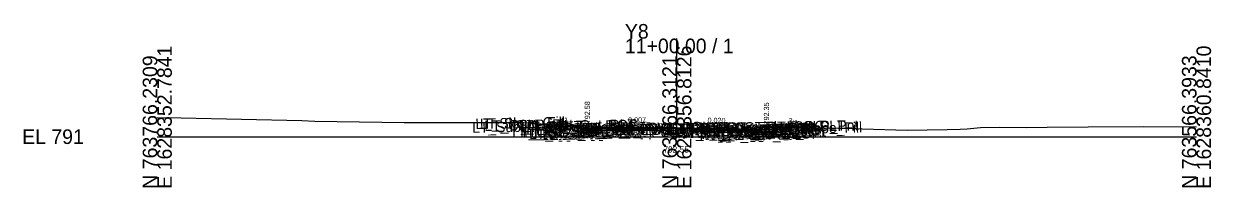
# Model space of a CAD drawing. Extents: x -26 to 203, y -10 to 3017.
# Drawn here: x -25.7 to 202.8, y 1990.3 to 2021.7 of the extents above; entities that cross this region are included whole.
import ezdxf

# ---------------------------------------------------------------- set-up
doc = ezdxf.new("R2010")
doc.units = 0
for name, color, linetype in [('Default', 7, 'Continuous'), ('Exist CMT Pavement', 7, 'Continuous'), ('Exist Cross Section Cell', 7, 'Continuous'), ('Exist XS Center Line Elevation Label', 7, 'Continuous'), ('Exist XS Ground Line', 7, 'Continuous'), ('Prop CMT Conc Surface', 7, 'Continuous'), ('Prop CMT Concrete Structures', 7, 'Continuous'), ('Prop CMT Pvmt Course 1', 7, 'Continuous'), ('Prop CMT Pvmt Course 1 CG', 7, 'Continuous'), ('Prop CMT Pvmt Course 1 Wedge', 7, 'Continuous'), ('Prop CMT Pvmt Course 2', 7, 'Continuous'), ('Prop CMT Pvmt Course 2 Wedge', 7, 'Continuous'), ('Prop CMT Pvmt Course 3', 7, 'Continuous'), ('Prop CMT Pvmt Surface', 7, 'Continuous'), ('Prop CMT Pvmt Wedge Surface 1', 7, 'Continuous'), ('Prop CMT Pvmt Wedge Surface 2', 7, 'Continuous'), ('Prop CMT Pvmt Wedge Surface 3', 7, 'Continuous'), ('Prop CMT Slope Grass', 7, 'Continuous'), ('Prop CMT Subgrade Earthwork', 7, 'Continuous'), ('Prop XS Hydro Elevations', 7, 'Continuous'), ('Prop XS SE Text', 7, 'Continuous'), ('Prop XS Side Slope Text', 7, 'Continuous'), ('Scratch_Level_0', 7, 'Continuous')]:
    doc.layers.add(name, color=color, linetype=linetype)

msp = doc.modelspace()

# ---------------------------------------------------------------- linework, layer by layer
at = {"layer": 'Exist CMT Pavement'}
for points in [[(100, 2001.55), (93.23, 2001.41), (84.89, 2001.1)], [(84.89, 2001.1), (84.89, 2001.1)], [(100, 2001.55), (100.57, 2001.56), (107.84, 2001.32), (115.19, 2000.98)], [(115.19, 2000.98), (115.19, 2000.98)]]:
    msp.add_lwpolyline(points, dxfattribs=at)
at = {"layer": 'Exist Cross Section Cell'}
for p, q in [((100, 2000), (100, 2018.82)), ((0, 2000), (100, 2000)), ((100, 2000), (200, 2000))]:
    msp.add_line(p, q, dxfattribs=at)
at = {"layer": 'Exist XS Ground Line'}
msp.add_lwpolyline([(0, 2003.66), (4.63, 2003.59), (27.82, 2003.09), (30.31, 2002.98), (47.52, 2002.72), (48.48, 2002.72), (50.58, 2002.75), (70.52, 2002.75), (77.54, 2002.17), (78.58, 2002.08), (79.01, 2001.99), (84.43, 2001.32), (84.89, 2001.1), (93.23, 2001.41), (100, 2001.55), (100.57, 2001.56), (107.84, 2001.32), (115.19, 2000.98), (115.49, 2001.2), (121.97, 2001.69), (123.33, 2001.81), (124.77, 2001.68), (131.01, 2001.66), (132.3, 2001.65), (133.19, 2001.64), (135.66, 2001.53), (144.34, 2001.26), (152.01, 2001.36), (154.53, 2001.46), (155.86, 2001.5), (158.44, 2001.75), (162.1, 2001.8), (167.2, 2001.78), (171.25, 2001.8), (179.17, 2001.9), (189.77, 2001.97), (200, 2001.91)], dxfattribs=at)
at = {"layer": 'Prop CMT Conc Surface'}
for points in [[(82.77, 2001.58), (82.77, 2002.08), (82.27, 2002.08)], [(84.77, 2001.67), (82.77, 2001.58)], [(115.24, 2001.47), (117.24, 2001.35)], [(117.24, 2001.35), (117.24, 2001.85), (117.74, 2001.85)]]:
    msp.add_lwpolyline(points, dxfattribs=at)
at = {"layer": 'Prop CMT Concrete Structures'}
for points in [[(84.77, 2001.67), (82.77, 2001.58), (82.77, 2002.08), (82.27, 2002.08)], [(82.27, 2002.08), (82.27, 2001.07), (84.77, 2001.09)], [(84.77, 2001.09), (84.77, 2001.67)], [(115.24, 2001.47), (117.24, 2001.35), (117.24, 2001.85), (117.74, 2001.85)], [(117.74, 2001.85), (117.74, 2000.84), (115.24, 2000.89)], [(115.24, 2000.89), (115.24, 2001.47)]]:
    msp.add_lwpolyline(points, dxfattribs=at)
at = {"layer": 'Prop CMT Pvmt Course 1'}
for points in [[(100, 2001.78), (84.77, 2001.67)], [(84.77, 2001.67), (84.77, 2001.42)], [(84.77, 2001.42), (84.89, 2001.43)], [(84.89, 2001.55), (100, 2001.65)], [(84.89, 2001.43), (84.89, 2001.55)], [(100, 2001.53), (100, 2001.78)], [(100, 2001.78), (115.24, 2001.47)], [(100, 2001.53), (100, 2001.78)], [(100, 2001.65), (100, 2001.53), (100, 2001.53)], [(115.19, 2001.35), (100, 2001.65)], [(100, 2001.65), (100, 2001.53), (100, 2001.53)], [(115.19, 2001.22), (115.19, 2001.35)], [(115.24, 2001.22), (115.19, 2001.22)], [(115.24, 2001.47), (115.24, 2001.22)]]:
    msp.add_lwpolyline(points, dxfattribs=at)
at = {"layer": 'Prop CMT Pvmt Course 1 CG'}
for points in [[(84.77, 2001.09), (81.77, 2001.07), (81.43, 2000.74)], [(81.43, 2000.74), (84.77, 2000.76)], [(84.77, 2000.76), (84.77, 2001.09)], [(115.24, 2000.89), (118.24, 2000.83), (118.58, 2000.49)], [(115.24, 2000.55), (115.24, 2000.89)], [(118.58, 2000.49), (115.24, 2000.55)]]:
    msp.add_lwpolyline(points, dxfattribs=at)
at = {"layer": 'Prop CMT Pvmt Course 1 Wedge'}
for points in [[(84.89, 2001.55), (93.23, 2001.61), (100, 2001.65)], [(84.89, 2001.55), (84.89, 2001.55)], [(100, 2001.55), (98.56, 2001.52), (93.23, 2001.48), (84.89, 2001.43)], [(84.89, 2001.43), (84.89, 2001.55)], [(84.89, 2001.43), (84.89, 2001.43)], [(100, 2001.65), (100, 2001.55)], [(100, 2001.65), (100.57, 2001.64), (107.84, 2001.49), (115.19, 2001.35)], [(100, 2001.55), (100, 2001.65)], [(115.19, 2001.22), (107.84, 2001.37), (103.95, 2001.45), (100.57, 2001.56), (100, 2001.55)], [(115.19, 2001.35), (115.19, 2001.22), (115.19, 2001.22)]]:
    msp.add_lwpolyline(points, dxfattribs=at)
at = {"layer": 'Prop CMT Pvmt Course 2'}
for points in [[(84.89, 2001.43), (84.77, 2001.42)], [(84.77, 2001.42), (84.77, 2001.09)], [(84.77, 2001.09), (84.89, 2001.09)], [(84.89, 2001.09), (84.89, 2001.43)], [(115.19, 2000.89), (115.19, 2001.22)], [(115.19, 2001.22), (115.24, 2001.22)], [(115.24, 2000.89), (115.19, 2000.89)], [(115.24, 2001.22), (115.24, 2000.89)]]:
    msp.add_lwpolyline(points, dxfattribs=at)
at = {"layer": 'Prop CMT Pvmt Course 2 Wedge'}
for points in [[(84.89, 2001.43), (93.23, 2001.48), (98.56, 2001.52)], [(98.56, 2001.52), (93.23, 2001.41), (84.89, 2001.1)], [(84.89, 2001.43), (84.89, 2001.43)], [(84.89, 2001.1), (84.89, 2001.43)], [(84.89, 2001.1), (84.89, 2001.1)], [(115.19, 2000.98), (107.84, 2001.32), (103.95, 2001.45)], [(103.95, 2001.45), (107.84, 2001.37)], [(107.84, 2001.37), (115.19, 2001.22)], [(115.19, 2001.22), (115.19, 2000.98), (115.19, 2000.98)]]:
    msp.add_lwpolyline(points, dxfattribs=at)
at = {"layer": 'Prop CMT Pvmt Course 3'}
for points in [[(84.89, 2001.09), (84.77, 2001.09)], [(84.77, 2001.09), (84.77, 2000.76)], [(84.77, 2000.76), (84.89, 2000.76)], [(84.89, 2000.76), (84.89, 2001.09)], [(115.19, 2000.89), (115.24, 2000.89)], [(115.19, 2000.56), (115.19, 2000.89)], [(115.24, 2000.55), (115.19, 2000.56)], [(115.24, 2000.89), (115.24, 2000.55)]]:
    msp.add_lwpolyline(points, dxfattribs=at)
at = {"layer": 'Prop CMT Pvmt Surface'}
for points in [[(100, 2001.78), (84.77, 2001.67)], [(100, 2001.78), (115.24, 2001.47)]]:
    msp.add_lwpolyline(points, dxfattribs=at)
at = {"layer": 'Prop CMT Pvmt Wedge Surface 1'}
for points in [[(84.77, 2001.42), (84.77, 2001.67)], [(84.89, 2001.43), (84.77, 2001.42)], [(100, 2001.65), (84.89, 2001.55)], [(84.89, 2001.55), (84.89, 2001.43)], [(100, 2001.65), (115.19, 2001.35)], [(115.19, 2001.35), (115.19, 2001.22)], [(115.19, 2001.22), (115.24, 2001.22)], [(115.24, 2001.22), (115.24, 2001.47)]]:
    msp.add_lwpolyline(points, dxfattribs=at)
at = {"layer": 'Prop CMT Pvmt Wedge Surface 2'}
for points in [[(84.77, 2001.42), (84.77, 2001.67)], [(100, 2001.53), (84.77, 2001.42)], [(100, 2001.53), (115.24, 2001.22)], [(115.24, 2001.22), (115.24, 2001.47)]]:
    msp.add_lwpolyline(points, dxfattribs=at)
at = {"layer": 'Prop CMT Pvmt Wedge Surface 3'}
for points in [[(84.77, 2001.09), (84.77, 2001.67)], [(100, 2001.19), (84.77, 2001.09)], [(100, 2001.19), (115.24, 2000.89)], [(115.24, 2000.89), (115.24, 2001.47)]]:
    msp.add_lwpolyline(points, dxfattribs=at)
at = {"layer": 'Prop CMT Slope Grass'}
for points in [[(78.77, 2002.15), (78.56, 2002.08)], [(82.27, 2002.08), (78.77, 2002.15)], [(117.74, 2001.85), (121.24, 2001.92)], [(121.24, 2001.92), (121.94, 2001.69)]]:
    msp.add_lwpolyline(points, dxfattribs=at)
at = {"layer": 'Prop CMT Subgrade Earthwork'}
for points in [[(84.77, 2000.76), (81.43, 2000.74), (80.04, 2002.13)], [(84.89, 2000.76), (84.77, 2000.76)], [(84.89, 2000.76), (84.91, 2001.1)], [(115.19, 2000.56), (115.17, 2000.98)], [(115.19, 2000.56), (115.24, 2000.55)], [(115.24, 2000.55), (118.58, 2000.49), (119.99, 2001.9)]]:
    msp.add_lwpolyline(points, dxfattribs=at)

# ---------------------------------------------------------------- texts
at = {"layer": 'Default'}
msp.add_text('-', height=0.0001, dxfattribs=at).set_placement((0, 2000))
at = {"layer": 'Exist Cross Section Cell'}
for s, p in [('Y8', (90, 2018.82)), ('11+00.00 / 1', (90, 2016.02)), ('EL 791', (-26, 1998.6))]:
    msp.add_text(s, height=2.8, dxfattribs=at).set_placement(p)
for s, p in [('E 1628352.7841', (2.8, 1990)), ('E 1628356.8126', (102.8, 1990)), ('E 1628360.8410', (202.8, 1990)), ('N 763766.2309', (0, 1990)), ('N 763666.3121', (100, 1990)), ('N 763566.3933', (200, 1990))]:
    msp.add_text(s, height=2.8, rotation=90, dxfattribs=at).set_placement(p)
at = {"layer": 'Exist XS Center Line Elevation Label'}
msp.add_text('792.55', height=1.2, dxfattribs=at).set_placement((97.41, 1996.95))
at = {"layer": 'Prop XS Hydro Elevations'}
for s, p in [('792.58', (83.27, 2002.58)), ('792.35', (117.74, 2002.35))]:
    msp.add_text(s, height=1, rotation=90, dxfattribs=at).set_placement(p)
at = {"layer": 'Prop XS SE Text'}
for s, rotation, p in [('0.007', 0.382, (90.62, 2002.71)), ('0.020', 358.8542, (105.89, 2002.66))]:
    msp.add_text(s, height=1, rotation=rotation, dxfattribs=at).set_placement(p)
at = {"layer": 'Prop XS Side Slope Text'}
for rotation, p in [(18.4332, (77.47, 2002.24)), (341.5668, (121.29, 2002.7))]:
    msp.add_text('3:1', height=1, rotation=rotation, dxfattribs=at).set_placement(p)
at = {"layer": 'Scratch_Level_0'}
for s, p in [('LT_Sub_Trench_Out_DLT', (60.63, 2000.74)), ('LT_Slope_Cut', (61.25, 2001.46)), ('LT_Slope_Fill', (62.13, 2001.48)), ('LT_CSLP_Pnt', (62.96, 2001.08)), ('LT_CG1_Shelf_Out', (68.34, 1999.8)), ('LT_PV_Sub_Tie_Out', (69.88, 1999.8)), ('LT_CG_Top_Face', (70.05, 2000.83)), ('LT_CG_Top_BOC', (70.57, 2000.85)), ('LT_CG_Bot_BOC', (70.6, 1999.84)), ('LT_CG_Top_Gut', (71.03, 2000.35)), ('LT_PV_OEEOP_EG', (72.46, 1999.85)), ('LT_PV2_OEEOP', (74.22, 2000.21)), ('LT_PV3_OEEOP', (74.22, 1999.88)), ('LT_CG_Bot_IE', (74.7, 1999.89)), ('LT_PV1_OEEOP', (74.79, 2000.35)), ('LT_PV2_OEOT', (74.96, 2000.23)), ('LT_PV3_OEOT', (74.96, 1999.9)), ('LT_PV1_OEOT', (75.53, 2000.49)), ('RT_PV_IEEOP_EG', (88.16, 2000.31)), ('LT_PV_IEEOP_EG', (88.21, 2000.31)), ('RT_PV2_IEEOP', (89.93, 2000.32)), ('RT_PV3_IEEOP', (89.93, 1999.99)), ('LT_PV2_IEEOP', (89.97, 2000.33)), ('LT_PV3_IEEOP', (89.97, 1999.99)), ('RT_PV1_IEEOP', (90.49, 2000.46)), ('LT_PV1_IEEOP', (90.54, 2000.46)), ('PV2_PGL', (93.93, 2000.4)), ('PV1_PGL', (94.49, 2000.67)), ('RT_PV_Sub_Tie_Out', (100.1, 1999.68)), ('RT_Sub_Trench_Out_DLT', (100.54, 2000.51)), ('RT_PV_OEEOP_EG', (102.71, 1999.73)), ('RT_PV2_OEEOP', (104.47, 2000.01)), ('RT_PV3_OEEOP', (104.47, 1999.67)), ('RT_CG_Top_Face', (104.48, 2000.6)), ('RT_CG1_Shelf_Out', (104.77, 1999.56)), ('RT_PV1_OEEOP', (105.04, 2000.14)), ('RT_CG_Bot_IE', (105.13, 1999.69)), ('RT_PV2_OEOT', (105.39, 2000.02)), ('RT_PV3_OEOT', (105.39, 1999.69)), ('RT_CG_Top_Gut', (105.45, 2000.12)), ('RT_PV1_OEOT', (105.96, 2000.29)), ('RT_CG_Top_BOC', (106, 2000.62)), ('RT_CG_Bot_BOC', (106.03, 1999.6)), ('RT_CSLP_Pnt', (117.39, 2000.84)), ('RT_Slope_Fill', (118.87, 2000.48)), ('LT_Sub_OEOP', (71.56, 1999.54)), ('LT_Sub_OEEOP', (74.13, 1999.54)), ('LT_Sub_OEOT', (74.87, 1999.56)), ('RT_Sub_OEEOP', (104.38, 1999.34)), ('RT_Sub_OEOT', (105.3, 1999.36)), ('RT_Sub_OEOP', (108.67, 1999.29))]:
    msp.add_text(s, height=2, rotation=1.1458, dxfattribs=at).set_placement(p)

doc.saveas('drawing.dxf')
